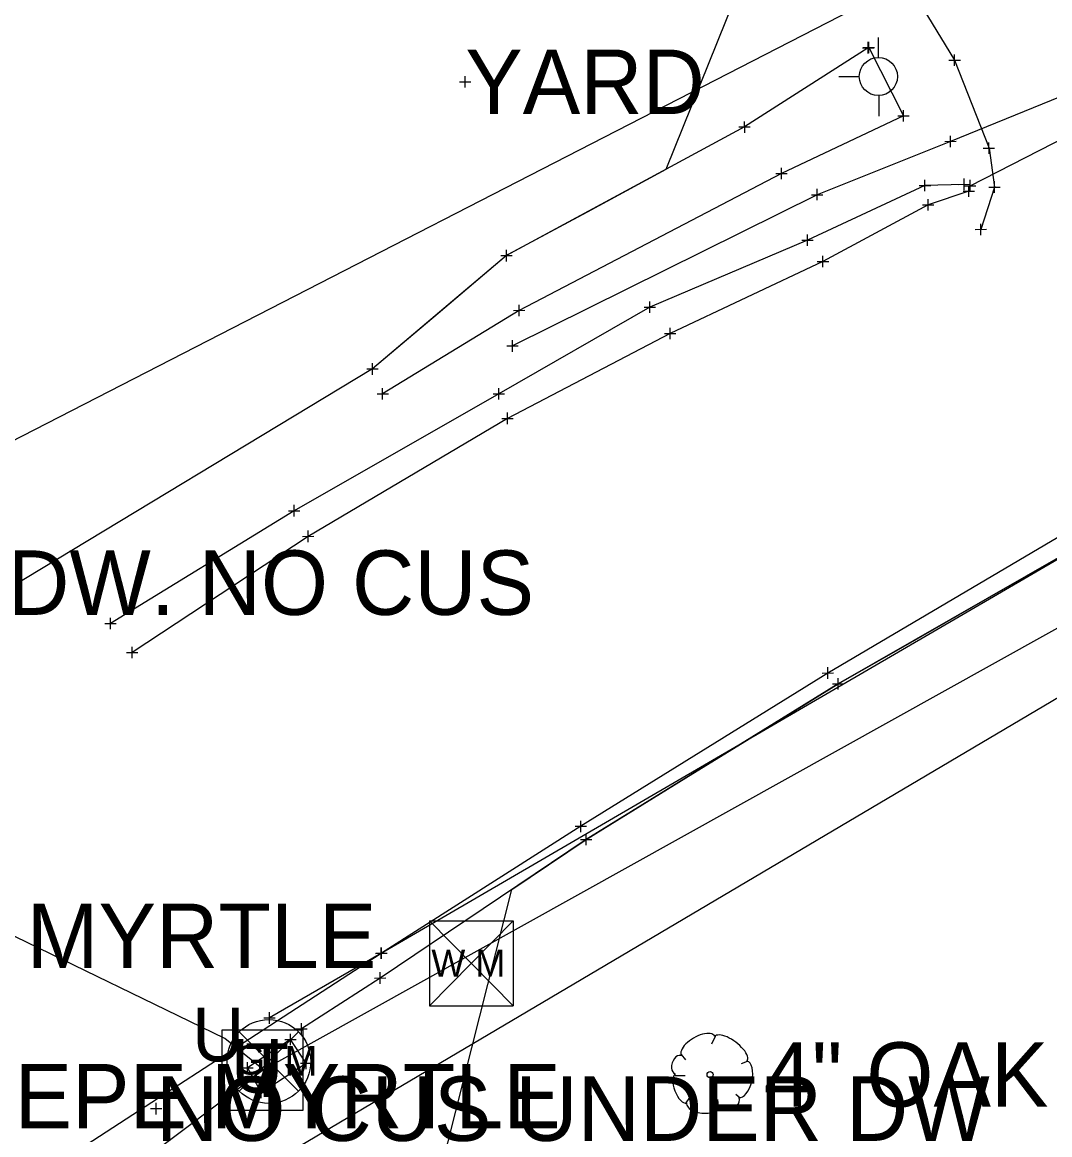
# Model space of a CAD drawing. Extents: x -1 to 1157254, y -1 to 2021979.
# Drawn here: x 1148433.7 to 1148548.4, y 2018129.3 to 2018253.6 of the extents above; entities that cross this region are included whole.
import ezdxf

# ---------------------------------------------------------------- set-up
doc = ezdxf.new("R2010")
doc.units = 0
for name, color, linetype in [('S_BUILDING_ANNOT', 7, 'Continuous'), ('S_CAL_CORNER_ANNOT', 7, 'Continuous'), ('S_CATCH_BASIN', 7, 'Continuous'), ('S_CATCH_BASIN_ANNOT', 7, 'Continuous'), ('S_CONTOUR_ANNOT', 7, 'Continuous'), ('S_CONTOUR_MAJOR', 7, 'Continuous'), ('S_CTL_TABLE', 7, 'Continuous'), ('S_CURB', 7, 'Continuous'), ('S_DRIVEWAY_ANNOT', 7, 'Continuous'), ('S_DROP_INLET', 7, 'Continuous'), ('S_DROP_INLET_ANNOT', 7, 'Continuous'), ('S_EDGE_BITUMINOUS_ANNOT', 7, 'Continuous'), ('S_ENV_CONSTRAINT', 7, 'Continuous'), ('S_EXISTING_ALIGNMENT', 7, 'Continuous'), ('S_FENCE', 7, 'Continuous'), ('S_GAS_PUMP_ISLAND_ANNOT', 7, 'Continuous'), ('S_GATE', 7, 'Continuous'), ('S_GATE_ANNOT', 7, 'Continuous')]:
    doc.layers.add(name, color=color, linetype=linetype)

msp = doc.modelspace()

# ---------------------------------------------------------------- linework, layer by layer
at = {"layer": 'S_BUILDING_ANNOT'}
for p, q in [((1148537.79, 2018248.7), (1148537.79, 2018249.97)), ((1148537.15, 2018249.33), (1148538.43, 2018249.34)), ((1148537.79, 2018249.34), (1148537.79, 2018249.34)), ((1148483.15, 2018246.28), (1148483.15, 2018247.55)), ((1148482.51, 2018246.92), (1148483.78, 2018246.92)), ((1148483.15, 2018246.92), (1148483.15, 2018246.92)), ((1148540.99, 2018239.51), (1148542.26, 2018239.51)), ((1148541.63, 2018238.87), (1148541.62, 2018240.14)), ((1148541.63, 2018239.51), (1148541.63, 2018239.51)), ((1148534.48, 2018234.69), (1148534.48, 2018235.96)), ((1148538.85, 2018234.83), (1148538.84, 2018236.1)), ((1148539.54, 2018234.68), (1148539.53, 2018235.95)), ((1148542.24, 2018234.53), (1148542.24, 2018235.8)), ((1148533.85, 2018235.32), (1148535.12, 2018235.32)), ((1148534.48, 2018235.32), (1148534.48, 2018235.32)), ((1148538.21, 2018235.46), (1148539.48, 2018235.47)), ((1148538.74, 2018234.71), (1148540.01, 2018234.71)), ((1148538.84, 2018235.46), (1148538.84, 2018235.46)), ((1148538.9, 2018235.31), (1148540.17, 2018235.31)), ((1148539.37, 2018234.07), (1148539.37, 2018235.35)), ((1148539.37, 2018234.71), (1148539.37, 2018234.71)), ((1148539.53, 2018235.31), (1148539.53, 2018235.31)), ((1148541.61, 2018235.16), (1148542.88, 2018235.16)), ((1148542.24, 2018235.16), (1148542.24, 2018235.16)), ((1148534.83, 2018232.54), (1148534.83, 2018233.81)), ((1148534.2, 2018233.17), (1148535.47, 2018233.17)), ((1148534.83, 2018233.17), (1148534.83, 2018233.17)), ((1148540.71, 2018229.8), (1148540.71, 2018231.07)), ((1148521.35, 2018228.58), (1148521.35, 2018229.85)), ((1148540.07, 2018230.43), (1148541.34, 2018230.44)), ((1148540.71, 2018230.43), (1148540.71, 2018230.43)), ((1148520.72, 2018229.21), (1148521.99, 2018229.21)), ((1148521.35, 2018229.21), (1148521.35, 2018229.21)), ((1148523.09, 2018226.21), (1148523.09, 2018227.48)), ((1148522.45, 2018226.84), (1148523.73, 2018226.85)), ((1148523.09, 2018226.84), (1148523.09, 2018226.84)), ((1148503.75, 2018221.11), (1148503.75, 2018222.39)), ((1148503.12, 2018221.75), (1148504.39, 2018221.75)), ((1148503.75, 2018221.75), (1148503.75, 2018221.75)), ((1148505.4, 2018218.81), (1148506.67, 2018218.81)), ((1148506.04, 2018218.17), (1148506.03, 2018219.45)), ((1148506.03, 2018218.81), (1148506.03, 2018218.81)), ((1148486.9, 2018211.43), (1148486.9, 2018212.7)), ((1148486.27, 2018212.06), (1148487.54, 2018212.07)), ((1148486.9, 2018212.07), (1148486.9, 2018212.07)), ((1148487.86, 2018208.68), (1148487.86, 2018209.96)), ((1148487.22, 2018209.32), (1148488.49, 2018209.32)), ((1148487.86, 2018209.32), (1148487.86, 2018209.32)), ((1148463.43, 2018199.01), (1148464.7, 2018199.01)), ((1148464.06, 2018198.37), (1148464.06, 2018199.65)), ((1148464.06, 2018199.01), (1148464.06, 2018199.01)), ((1148464.98, 2018196.14), (1148466.25, 2018196.15)), ((1148465.62, 2018195.51), (1148465.61, 2018196.78)), ((1148465.62, 2018196.14), (1148465.62, 2018196.14)), ((1148442.9, 2018186.42), (1148444.17, 2018186.42)), ((1148443.54, 2018185.78), (1148443.54, 2018187.05)), ((1148443.54, 2018186.42), (1148443.54, 2018186.42)), ((1148445.97, 2018182.53), (1148445.96, 2018183.8)), ((1148445.33, 2018183.17), (1148446.6, 2018183.17)), ((1148445.97, 2018183.17), (1148445.97, 2018183.17)), ((1148523.63, 2018180.24), (1148523.63, 2018181.51)), ((1148523, 2018180.87), (1148524.27, 2018180.88)), ((1148523.63, 2018180.87), (1148523.63, 2018180.87)), ((1148524.8, 2018179.03), (1148524.79, 2018180.31)), ((1148524.16, 2018179.67), (1148525.43, 2018179.67)), ((1148524.8, 2018179.67), (1148524.8, 2018179.67)), ((1148495.42, 2018163.75), (1148496.69, 2018163.75)), ((1148496.06, 2018163.11), (1148496.05, 2018164.38)), ((1148496.06, 2018163.75), (1148496.06, 2018163.75)), ((1148496.65, 2018161.64), (1148496.65, 2018162.91)), ((1148496.02, 2018162.27), (1148497.29, 2018162.28)), ((1148496.65, 2018162.28), (1148496.65, 2018162.28)), ((1148473.78, 2018148.93), (1148473.78, 2018150.2)), ((1148473.8, 2018148.94), (1148473.8, 2018150.21)), ((1148473.14, 2018149.56), (1148474.41, 2018149.57)), ((1148473.17, 2018149.58), (1148474.44, 2018149.58)), ((1148473.78, 2018149.56), (1148473.78, 2018149.56)), ((1148473.8, 2018149.58), (1148473.8, 2018149.58)), ((1148473.02, 2018146.8), (1148474.29, 2018146.81)), ((1148473.66, 2018146.17), (1148473.66, 2018147.44)), ((1148473.66, 2018146.8), (1148473.66, 2018146.8)), ((1148461.31, 2018141.7), (1148461.3, 2018142.98)), ((1148460.67, 2018142.34), (1148461.94, 2018142.34)), ((1148461.31, 2018142.34), (1148461.31, 2018142.34)), ((1148464.88, 2018140.47), (1148464.87, 2018141.75)), ((1148463.63, 2018139.29), (1148463.63, 2018140.56)), ((1148464.24, 2018141.11), (1148465.51, 2018141.11)), ((1148464.88, 2018141.11), (1148464.88, 2018141.11)), ((1148463, 2018139.93), (1148464.27, 2018139.93)), ((1148463.63, 2018139.93), (1148463.63, 2018139.93)), ((1148465.37, 2018136.64), (1148465.37, 2018137.91)), ((1148458.19, 2018136.76), (1148459.46, 2018136.76)), ((1148458.83, 2018136.12), (1148458.83, 2018137.39)), ((1148458.83, 2018136.76), (1148458.83, 2018136.76)), ((1148464.74, 2018137.28), (1148466.01, 2018137.28)), ((1148465.37, 2018137.28), (1148465.37, 2018137.28)), ((1148459.71, 2018134), (1148460.98, 2018134.01)), ((1148460.35, 2018133.37), (1148460.35, 2018134.64)), ((1148460.35, 2018134.01), (1148460.35, 2018134.01)), ((1148448.64, 2018131.57), (1148448.63, 2018132.85)), ((1148448, 2018132.21), (1148449.27, 2018132.21)), ((1148448.63, 2018132.21), (1148448.63, 2018132.21))]:
    msp.add_line(p, q, dxfattribs=at)
at = {"layer": 'S_CAL_CORNER_ANNOT'}
for p, q in [((1148457.92, 2018134.18), (1148464.53, 2018140.79)), ((1148457.92, 2018140.79), (1148464.53, 2018134.18))]:
    msp.add_line(p, q, dxfattribs=at)
msp.add_lwpolyline([(1148912.94, 2018389.54), (1148884.02, 2018371.37), (1148841.26, 2018349), (1148782.55, 2018319.82), (1148727.8, 2018292.18), (1148687.32, 2018271.68), (1148647.96, 2018251.03), (1148473.78, 2018149.56), (1148431.39, 2018121.98), (1148409.2, 2018106.42), (1148303.97, 2018024.03), (1148255.75, 2017987.09), (1148260.87, 2017979.68), (1148255.56, 2017975.26), (1148250.28, 2017982.33), (1148176.11, 2017926.04), (1148136.14, 2017895.28)], dxfattribs=at)
msp.add_circle((1148461.23, 2018137.48), 4.68, dxfattribs=at)
at = {"layer": 'S_CATCH_BASIN'}
for p, q in [((1148529.28, 2018249.62), (1148529.28, 2018251.87)), ((1148527.18, 2018247.49), (1148524.86, 2018247.49)), ((1148529.35, 2018243.07), (1148529.35, 2018245.4))]:
    msp.add_line(p, q, dxfattribs=at)
msp.add_circle((1148529.28, 2018247.51), 2.13, dxfattribs=at)
at = {"layer": 'S_CATCH_BASIN_ANNOT'}
msp.add_lwpolyline([(1148456, 2018132.02), (1148456, 2018141.01), (1148465, 2018141.01), (1148465, 2018132.02)], close=True, dxfattribs=at)
at = {"layer": 'S_CONTOUR_ANNOT'}
for p, q in [((1148479.17, 2018153.19), (1148488.5, 2018153.19)), ((1148479.17, 2018153.19), (1148479.17, 2018143.7)), ((1148479.17, 2018153.19), (1148488.5, 2018143.7)), ((1148488.5, 2018153.19), (1148479.17, 2018143.7)), ((1148488.5, 2018153.19), (1148488.5, 2018143.7)), ((1148479.17, 2018143.7), (1148488.5, 2018143.7))]:
    msp.add_line(p, q, dxfattribs=at)
msp.add_lwpolyline([(1149931.59, 2019393.98), (1149688.42, 2019230.92), (1149605.65, 2019167.39), (1149471.25, 2019025.78), (1149394.11, 2018934.21), (1149347.84, 2018899.68), (1149226.01, 2018779.47), (1149177.83, 2018729.86), (1148942.89, 2018495.75), (1148824.88, 2018414.4), (1148656.17, 2018321.62), (1148428.99, 2018204.95), (1148398.58, 2018185.48), (1148319.88, 2018123.12), (1148171.01, 2018007.64), (1148133.82, 2017978.13)], dxfattribs=at)
at = {"layer": 'S_CTL_TABLE'}
for p, q in [((1148527.5, 2018250.73), (1148528.78, 2018250.73)), ((1148527.57, 2018250.76), (1148528.84, 2018250.76)), ((1148528.14, 2018250.09), (1148528.14, 2018251.37)), ((1148528.14, 2018250.73), (1148528.14, 2018250.73)), ((1148528.21, 2018250.13), (1148528.21, 2018251.4)), ((1148528.21, 2018250.76), (1148528.21, 2018250.76)), ((1148532.08, 2018242.48), (1148532.07, 2018243.76)), ((1148514.35, 2018241.23), (1148514.34, 2018242.5)), ((1148531.44, 2018243.12), (1148532.71, 2018243.12)), ((1148532.08, 2018243.12), (1148532.08, 2018243.12)), ((1148513.71, 2018241.87), (1148514.98, 2018241.87)), ((1148514.34, 2018241.87), (1148514.34, 2018241.87)), ((1148537.33, 2018239.63), (1148537.32, 2018240.9)), ((1148536.69, 2018240.26), (1148537.96, 2018240.27)), ((1148537.33, 2018240.26), (1148537.33, 2018240.26)), ((1148518.46, 2018236.04), (1148518.45, 2018237.32)), ((1148517.82, 2018236.68), (1148519.09, 2018236.68)), ((1148518.46, 2018236.68), (1148518.46, 2018236.68)), ((1148522.44, 2018233.68), (1148522.44, 2018234.95)), ((1148521.81, 2018234.31), (1148523.08, 2018234.31)), ((1148522.44, 2018234.31), (1148522.44, 2018234.31)), ((1148487.11, 2018227.5), (1148488.38, 2018227.5)), ((1148487.75, 2018226.86), (1148487.74, 2018228.13)), ((1148487.75, 2018227.5), (1148487.75, 2018227.5)), ((1148488.55, 2018221.38), (1148489.82, 2018221.39)), ((1148489.18, 2018220.75), (1148489.18, 2018222.02)), ((1148489.18, 2018221.38), (1148489.18, 2018221.38)), ((1148487.79, 2018217.41), (1148489.06, 2018217.41)), ((1148488.42, 2018216.77), (1148488.42, 2018218.05)), ((1148488.42, 2018217.41), (1148488.42, 2018217.41)), ((1148472.16, 2018214.84), (1148473.43, 2018214.84)), ((1148472.8, 2018214.2), (1148472.79, 2018215.48)), ((1148472.8, 2018214.84), (1148472.8, 2018214.84)), ((1148473.93, 2018211.43), (1148473.93, 2018212.7)), ((1148473.3, 2018212.06), (1148474.57, 2018212.06)), ((1148473.93, 2018212.06), (1148473.93, 2018212.06))]:
    msp.add_line(p, q, dxfattribs=at)
at = {"layer": 'S_CURB'}
for p, q in [((1148511.05, 2018140.27), (1148510.66, 2018139.41)), ((1148507.25, 2018138.25), (1148507.75, 2018137.67)), ((1148514.61, 2018137.48), (1148513.95, 2018137.21)), ((1148506.59, 2018135.93), (1148507.72, 2018135.93)), ((1148507.75, 2018132.75), (1148508.22, 2018133.45)), ((1148511.43, 2018132.48), (1148511.36, 2018133.25)), ((1148513.84, 2018133.37), (1148513.37, 2018133.8))]:
    msp.add_line(p, q, dxfattribs=at)
msp.add_circle((1148510.49, 2018136.02), 0.34, dxfattribs=at)
for centre, major_axis, ratio, start_param, end_param in [((1148509.15, 2018139.22), (1.86, 1.08), 0.471018, 0, 3.141593), ((1148512.81, 2018138.9), (-1.81, 1.36), 0.405113, 3.141593, 6.283186), ((1148506.92, 2018137.11), (0.31, 1.03), 0.646762, 0, 3.141593), ((1148514.16, 2018135.49), (0.46, 2.04), 0.482994, 3.141593, 6.283185), ((1148507.23, 2018134.46), (-0.61, 1.6), 0.420543, 6.283185, 9.424777), ((1148509.68, 2018132.68), (-1.83, 0.19), 0.529943, 0, 3.141593), ((1148512.64, 2018132.97), (1.09, 0.46), 0.711534, 3.141592, 6.283185)]:
    msp.add_ellipse(centre, major_axis=major_axis, ratio=ratio, start_param=start_param, end_param=end_param, dxfattribs=at)
at = {"layer": 'S_DRIVEWAY_ANNOT'}
for points in [[(1148647.18, 2018247.07), (1148645.2, 2018246.18), (1148638.79, 2018243.62), (1148626.14, 2018238.95), (1148603.81, 2018226.97), (1148576.29, 2018212), (1148549.3, 2018196.03), (1148523.63, 2018180.87), (1148496.06, 2018163.75), (1148473.8, 2018149.58), (1148461.31, 2018142.34)], [(1148647.85, 2018246.05), (1148646.29, 2018245), (1148640.55, 2018242.35), (1148628.24, 2018237.67), (1148604.47, 2018225.85), (1148577.06, 2018210.96), (1148549.89, 2018194.05), (1148524.8, 2018179.67), (1148496.65, 2018162.28), (1148473.66, 2018146.8), (1148464.88, 2018141.11)], [(1148538.84, 2018235.46), (1148534.48, 2018235.32), (1148521.35, 2018229.21), (1148503.75, 2018221.75), (1148486.9, 2018212.07), (1148464.06, 2018199.01), (1148443.54, 2018186.42)], [(1148539.37, 2018234.71), (1148534.83, 2018233.17), (1148523.09, 2018226.84), (1148506.03, 2018218.81), (1148487.86, 2018209.32), (1148465.62, 2018196.14), (1148445.97, 2018183.17)]]:
    msp.add_lwpolyline(points, dxfattribs=at)
at = {"layer": 'S_DROP_INLET'}
for points in [[(1149478.88, 2018922.64), (1149385.84, 2018831.36), (1149330.57, 2018775.16), (1149250.6, 2018696.8), (1149231.5, 2018678.75), (1149169.67, 2018614.3), (1149128.45, 2018577.04), (1149075.89, 2018529.44), (1149016.28, 2018476.33), (1148941.34, 2018408.7), (1148861.11, 2018354.7), (1148778.49, 2018311.96), (1148755.86, 2018297.95), (1148577.39, 2018201.52), (1148460.64, 2018136.54), (1148334.57, 2018041.74), (1148195.53, 2017935.77), (1148138.82, 2017892.99)], [(1148460.64, 2018136.54), (1148456.29, 2018140.04), (1148406.91, 2018164.01)]]:
    msp.add_lwpolyline(points, dxfattribs=at)
at = {"layer": 'S_DROP_INLET_ANNOT'}
msp.add_lwpolyline([(1148539.53, 2018235.31), (1148561.17, 2018246.39)], dxfattribs=at)
at = {"layer": 'S_EDGE_BITUMINOUS_ANNOT'}
for points in [[(1148528.14, 2018250.73), (1148514.34, 2018241.87), (1148487.75, 2018227.5), (1148472.8, 2018214.84)], [(1148528.21, 2018250.76), (1148532.08, 2018243.12), (1148518.46, 2018236.68), (1148489.18, 2018221.38), (1148473.93, 2018212.06)], [(1148560.82, 2018249.83), (1148537.33, 2018240.26), (1148522.44, 2018234.31), (1148488.42, 2018217.41)]]:
    msp.add_lwpolyline(points, dxfattribs=at)
at = {"layer": 'S_ENV_CONSTRAINT'}
msp.add_lwpolyline([(1148521.81, 2018277.52), (1148529.25, 2018263.36), (1148537.79, 2018249.34), (1148541.63, 2018239.51), (1148542.24, 2018235.16), (1148540.71, 2018230.43)], dxfattribs=at)
at = {"layer": 'S_EXISTING_ALIGNMENT'}
msp.add_lwpolyline([(1148460.35, 2018134.01), (1148465.37, 2018137.28), (1148463.63, 2018139.93), (1148458.83, 2018136.76)], close=True, dxfattribs=at)
at = {"layer": 'S_FENCE'}
msp.add_lwpolyline([(1149562.21, 2019005.4), (1149486.21, 2018927.15), (1149466.96, 2018916.4), (1149448.15, 2018887.45), (1149385.38, 2018826.9), (1149357.5, 2018803.66), (1149334.17, 2018772.97), (1149278.68, 2018714.02), (1149266.21, 2018707.99), (1149250.6, 2018696.75), (1149241.46, 2018677.2), (1149179.13, 2018611.74), (1149130.37, 2018567.15), (1149080.16, 2018520.92), (1149020.19, 2018471.53), (1148946.08, 2018397.31), (1148842.28, 2018340.54), (1148783.26, 2018310.71), (1148755.06, 2018299.13), (1148580.09, 2018196.31), (1148464.77, 2018128.06), (1148357.29, 2018049.22), (1148182.05, 2017918.06), (1148146.03, 2017882.74)], dxfattribs=at)
at = {"layer": 'S_GAS_PUMP_ISLAND_ANNOT'}
for points in [[(1148647.21, 2018312.02), (1148626.66, 2018305.86), (1148618.55, 2018300.02), (1148610.43, 2018294.18), (1148602.32, 2018288.33), (1148597.29, 2018284.71), (1148588.99, 2018279.14), (1148540.53, 2018272.33), (1148521.81, 2018277.52), (1148505.55, 2018237.11), (1148496.75, 2018232.36), (1148487.95, 2018227.61), (1148487.75, 2018227.5), (1148480.12, 2018221.04), (1148472.8, 2018214.84), (1148432.28, 2018190.34)], [(1148476.73, 2018110.72), (1148488.36, 2018156.7), (1148496.65, 2018162.28), (1148499.29, 2018163.9), (1148507.79, 2018169.16), (1148516.29, 2018174.41), (1148524.8, 2018179.67), (1148532.55, 2018184.11), (1148541.22, 2018189.08), (1148549.89, 2018194.05), (1148551.61, 2018195.12), (1148560.09, 2018200.4), (1148568.58, 2018205.68), (1148577.06, 2018210.96), (1148578.14, 2018211.55), (1148586.92, 2018216.31), (1148595.7, 2018221.08), (1148643.98, 2018208.64)]]:
    msp.add_lwpolyline(points, dxfattribs=at)

# ---------------------------------------------------------------- texts
at = {"layer": 'S_CAL_CORNER_ANNOT'}
for s, p in [('G', (1148457.41, 2018136.02)), ('M', (1148462.97, 2018135.91))]:
    msp.add_text(s, height=3.3, dxfattribs=at).set_placement(p)
at = {"layer": 'S_CATCH_BASIN_ANNOT'}
msp.add_text('T', height=6, dxfattribs=at).set_placement((1148458.56, 2018133.52))
at = {"layer": 'S_CONTOUR_ANNOT'}
msp.add_text('W M', height=2.999, dxfattribs=at).set_placement((1148479.37, 2018146.96))
at = {"layer": 'S_CONTOUR_MAJOR'}
for p in [(1148452.66, 2018137.5), (1148457.02, 2018134), (1148457.02, 2018134)]:
    msp.add_text('U', height=6, dxfattribs=at).set_placement(p)
at = {"layer": 'S_GATE'}
for s, p in [('YARD', (1148483.15, 2018243.32)), ('GR DW. NO CUS', (1148414.88, 2018187.37)), ('NO CUS UNDER DW', (1148448.63, 2018128.61))]:
    msp.add_text(s, height=7.2, dxfattribs=at).set_placement(p)
at = {"layer": 'S_GATE_ANNOT'}
for s, p in [('3" CREPE MYRTLE', (1148386.89, 2018147.91)), ('4" OAK', (1148516.49, 2018132.42)), ('CLUSTER 2" CREPE MYRTLE', (1148359.85, 2018130))]:
    msp.add_text(s, height=7.2, dxfattribs=at).set_placement(p)

doc.saveas('drawing.dxf')
